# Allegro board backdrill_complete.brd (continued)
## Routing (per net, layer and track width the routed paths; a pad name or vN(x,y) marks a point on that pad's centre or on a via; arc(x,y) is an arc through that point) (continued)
P66_AD3: length 22.9
  TOP w0.127: 31.75,67.31 17.86,67.31 16.9,66.36 16.12,66.36 15.16,67.31 11.43,67.31 ; 53.15,32.58 U3D1.D2 53.31,32.44 52.73,33.02 53.02,32.72 53.15,32.59 53.15,32.58
P66_AD4: length 22.9
  TOP w0.127: 52.73,31.75 53.02,31.45 53.15,31.32 53.15,31.31 U3D1.E2 53.31,31.17 52.73,31.75
  LAYER_8 w0.127: 19.05,68.58 32.94,68.58 33.9,67.63 34.68,67.63 35.64,68.58 39.37,68.58
P66_AD5: length 22.9
  TOP w0.127: 13.97,68.58 17.7,68.58 18.66,67.63 19.44,67.63 20.4,68.58 34.29,68.58 ; 53.31,33.71 52.73,34.29 53.02,33.99 53.15,33.86 53.15,33.85 U3D1.C2 53.31,33.71
P66_AD6: length 22.9
  TOP w0.127: 16.51,69.85 30.4,69.85 31.36,68.9 32.14,68.9 33.1,69.85 36.83,69.85 ; U3D1.B2 53.31,34.98 52.73,35.56 53.02,35.26 53.15,35.13 53.15,35.12 U3D1.B2
P66_AD7: length 22.9
  TOP w0.127: 53.02,36.53 52.73,36.83 53.31,36.25 U3D1.A2 53.15,36.39 53.15,36.4 53.02,36.53
  BOTTOM w0.127: 13.97,71.12 17.7,71.12 18.66,70.17 19.44,70.17 20.4,71.12 34.29,71.12
P66_AD8: length 22.9
  TOP w0.127: 54,31.75 54.58,31.17 U3D1.E3 54.42,31.31 54.42,31.32 54.29,31.45 54,31.75
  LAYER_8 w0.127: 11.43,72.39 15.16,72.39 16.12,71.44 16.9,71.44 17.86,72.39 31.75,72.39
P66_AD9: length 22.9
  TOP w0.127: 54,35.56 54.58,34.98 U3D1.B3 54.42,35.12 54.42,35.13 54.29,35.26 54,35.56
  LAYER_8 w0.127: 39.37,76.2 35.64,76.2 34.68,75.25 33.9,75.25 32.94,76.2 19.05,76.2
P66_AD10: length 22.9
  TOP w0.127: 55.56,32.72 55.27,33.02 55.85,32.44 U3D1.D4 55.69,32.58 55.69,32.59 55.56,32.72
  BOTTOM w0.127: 31.75,77.47 19.74,77.47 19.71,77.44 17.83,77.44 16.9,76.52 16.12,76.52 15.16,77.47 11.43,77.47
P66_AD11: length 22.9
  TOP w0.127: 55.27,31.75 55.85,31.17 U3D1.E4 55.69,31.31 55.69,31.32 55.56,31.45 55.27,31.75
  LAYER_8 w0.127: 39.37,78.74 35.64,78.74 34.68,77.79 33.9,77.79 32.94,78.74 19.05,78.74
P66_AD12: length 22.9
  TOP w0.127: 55.27,34.29 55.85,33.71 U3D1.C4 55.69,33.85 55.69,33.86 55.56,33.99 55.27,34.29
  BOTTOM w0.127: 13.97,78.74 17.55,78.74 18.54,77.75 19.58,77.75 20.57,78.74 34.29,78.74
P66_AD13: length 22.9
  TOP w0.127: 55.69,35.12 55.69,35.13 55.56,35.26 55.27,35.56 55.85,34.98 U3D1.B4 55.69,35.12
  BOTTOM w0.127: 16.51,80.01 30.4,80.01 31.36,79.06 32.14,79.06 33.1,80.01 36.83,80.01
P66_AD14: length 22.9
  TOP w0.127: 55.85,36.25 55.27,36.83 55.56,36.53 55.69,36.4 55.69,36.39 U3D1.A4 55.85,36.25
  BOTTOM w0.127: 13.97,81.28 17.7,81.28 18.66,80.33 19.44,80.33 20.4,81.28 34.29,81.28
P66_AD15: length 22.9
  TOP w0.127: 56.96,35.13 56.83,35.26 56.54,35.56 57.12,34.98 U3D1.B5 56.96,35.12 56.96,35.13
  LAYER_8 w0.127: 16.51,82.55 30.4,82.55 31.36,81.6 32.14,81.6 33.1,82.55 36.83,82.55
P66_AD16: length 22.9
  TOP w0.127: U3D1.D9 62.2,32.44 61.62,33.02 61.91,32.72 62.04,32.59 62.04,32.58 U3D1.D9
  LAYER_8 w0.127: 36.83,97.79 33.1,97.79 32.14,96.84 31.36,96.84 30.4,97.79 16.51,97.79
P66_AD17: length 22.9
  TOP w0.127: U3D1.C9 62.2,33.71 61.62,34.29 61.91,33.99 62.04,33.86 62.04,33.85 U3D1.C9
  LAYER_5 w0.127: 31.75,97.79 17.86,97.79 16.9,96.84 16.12,96.84 15.16,97.79 11.43,97.79
P66_AD18: length 22.9
  TOP w0.127: 62.04,36.4 61.91,36.53 61.62,36.83 62.2,36.25 U3D1.A9 62.04,36.39 62.04,36.4
  LAYER_5 w0.127: 19.05,99.06 32.94,99.06 33.9,98.11 34.68,98.11 35.64,99.06 39.37,99.06
P66_AD19: length 22.9
  TOP w0.127: 63.69,32.58 63.69,32.59 63.82,32.72 64.11,33.02 63.53,32.44 U3D1.D10 63.69,32.58
  LAYER_5 w0.127: 31.75,100.33 17.86,100.33 16.9,99.38 16.12,99.38 15.16,100.33 11.43,100.33
P66_AD20: length 22.9
  TOP w0.127: 64.11,34.29 63.82,33.99 63.69,33.86 63.69,33.85 U3D1.C10 63.53,33.71 64.11,34.29
  LAYER_8 w0.127: 19.05,101.6 32.94,101.6 33.9,100.65 34.68,100.65 35.64,101.6 39.37,101.6
P66_AD21: length 22.9
  TOP w0.127: 64.11,35.56 63.53,34.98 U3D1.B10 63.69,35.12 63.69,35.13 63.82,35.26 64.11,35.56
  LAYER_5 w0.127: 13.97,101.6 17.7,101.6 18.66,100.65 19.44,100.65 20.4,101.6 34.29,101.6
P66_AD22: length 22.9
  TOP w0.127: 64.11,36.83 63.82,36.53 63.69,36.4 63.69,36.39 U3D1.A10 63.53,36.25 64.11,36.83
  LAYER_3 w0.127: 36.83,102.87 33.1,102.87 32.14,101.92 31.36,101.92 30.4,102.87 16.51,102.87
P66_AD23: length 22.9
  TOP w0.127: U3D1.D11 64.96,32.58 64.96,32.59 65.09,32.72 65.38,33.02 64.8,32.44 U3D1.D11
  LAYER_3 w0.127: 34.29,104.14 20.4,104.14 19.44,103.19 18.66,103.19 17.7,104.14 13.97,104.14
P66_AD24: length 22.9
  TOP w0.127: 64.96,35.12 64.96,35.13 65.09,35.26 65.38,35.56 64.8,34.98 U3D1.B11 64.96,35.12
  LAYER_8 w0.127: 19.05,106.68 32.94,106.68 33.9,105.73 34.68,105.73 35.64,106.68 39.37,106.68
P66_AD25: length 22.9
  TOP w0.127: 65.38,36.83 65.09,36.53 64.96,36.4 64.96,36.39 U3D1.A11 64.8,36.25 65.38,36.83
  LAYER_3 w0.127: 31.75,107.95 17.86,107.95 16.9,107 16.12,107 15.16,107.95 11.43,107.95
P66_AD26: length 124.8
  TOP w0.127: 66.36,32.72 66.65,33.02 66.07,32.44 U3D1.D12 66.23,32.58 66.23,32.59 66.36,32.72
  LAYER_6 w0.127: 66.65,33.02 66.83,33.2 66.83,33.75 67.16,34.08 67.16,37.04 66.83,37.37 66.83,38.51 66.7,38.63 42.9,38.63 40.61,40.92 40.61,108.03 39.42,109.22 39.37,109.22
  LAYER_8 w0.127: 39.37,109.22 35.64,109.22 34.68,108.27 33.9,108.27 32.94,109.22 19.05,109.22
P66_AD27: length 22.9
  TOP w0.127: 34.29,109.22 20.4,109.22 19.44,108.27 18.66,108.27 17.7,109.22 13.97,109.22 ; U3D1.C12 66.23,33.85 66.23,33.86 66.36,33.99 66.65,34.29 66.07,33.71 U3D1.C12
P66_AD28: length 22.9
  TOP w0.127: 36.83,110.49 33.1,110.49 32.14,109.54 31.36,109.54 30.4,110.49 16.51,110.49 ; U3D1.A12 66.07,36.25 66.65,36.83 66.36,36.53 66.23,36.4 66.23,36.39 U3D1.A12
P66_AD29: length 22.9
  TOP w0.127: 34.29,111.76 20.4,111.76 19.44,110.81 18.66,110.81 17.7,111.76 13.97,111.76 ; 67.34,33.71 U3D1.C13 67.5,33.85 67.5,33.86 67.63,33.99 67.92,34.29 67.34,33.71
P66_AD30: length 22.8
  TOP w0.127: 67.34,34.98 U3D1.B13 67.5,35.12 67.5,35.13 67.63,35.26 67.92,35.56 67.34,34.98
  LAYER_8 w0.127: 16.51,113.03 30.45,113.03 31.37,112.12 32.11,112.12 33.02,113.03 36.83,113.03
P66_AD31: length 22.9
  TOP w0.127: 31.75,113.03 17.86,113.03 16.9,112.08 16.12,112.08 15.16,113.03 11.43,113.03 ; 67.5,36.39 U3D1.A13 67.34,36.25 67.92,36.83 67.63,36.53 67.5,36.4 67.5,36.39
P66_AD32: length 37.5
  TOP w0.127: 19.05,20.32 32.94,20.32 33.9,19.37 34.68,19.37 35.64,20.32 47.12,20.32 50.8,16.64 52.19,16.64 52.51,16.96 52.51,17.34 52.83,17.65 U3D1.T2
P66_AD33: length 44.1
  TOP w0.127: 51.46,17.73 52.04,17.14 U3D1.T1
  LAYER_5 w0.127: 31.75,21.59 17.86,21.59 16.9,20.64 16.12,20.64 15.16,21.59 11.43,21.59
  LAYER_8 w0.127: 31.75,21.59 35.48,21.59 36.44,20.64 37.22,20.64 38.18,21.59 47.6,21.59 51.46,17.73
P66_AD34: length 22
  TOP w0.127: 55.88,18.41 55.8,18.41 55.25,18.97 55.3,19.02
  LAYER_3 w0.127: 39.37,22.86 35.64,22.86 34.68,21.91 33.9,21.91 32.94,22.86 19.05,22.86
P66_AD35: length 44.2
  TOP w0.127: 54.05,19 54.64,18.41 54.61,18.41
  LAYER_5 w0.127: 13.97,22.86 17.7,22.86 18.66,21.91 19.44,21.91 20.4,22.86 34.29,22.86
  LAYER_8 w0.127: 54.05,19 53.92,18.87 53.17,18.87 52.84,18.54 51.08,18.54 47.07,22.56 40.41,22.56 39.76,21.91 38.98,21.91 38.02,22.86 34.29,22.86
P66_AD36: length 22.1
  TOP w0.127: 53.26,18.52 53.24,18.52 ; 53.26,18.52 53.34,18.41 ; 53.26,18.52 52.68,19.1
  LAYER_5 w0.127: 36.83,24.13 33.1,24.13 32.14,23.18 31.36,23.18 30.4,24.13 16.51,24.13
P66_AD37: length 44.3
  TOP w0.127: 52.07,18.41 52.04,18.47 51.46,19.05 51.75,18.75 51.88,18.62 51.88,18.61 52.07,18.41
  LAYER_5 w0.127: 34.29,25.4 20.4,25.4 19.44,24.45 18.66,24.45 17.7,25.4 13.97,25.4
  LAYER_8 w0.127: 51.46,19.05 46.37,24.14 38.19,24.14 37.22,23.18 36.44,23.18 35.88,23.74 35.88,25.22 35.7,25.4 34.29,25.4
P66_AD38: length 22.9
  TOP w0.127: 55.69,19.89 55.69,19.88 U3D1.P4 55.85,19.74 55.27,20.32 55.56,20.02 55.69,19.89
  LAYER_3 w0.127: 16.51,26.67 30.4,26.67 31.36,25.72 32.14,25.72 33.1,26.67 36.83,26.67
P66_AD39: length 48.5
  TOP w0.127: 54.58,19.74 54,20.32 54.29,20.02 54.42,19.89 54.42,19.88 U3D1.P3 54.58,19.74
  LAYER_5 w0.127: 31.75,26.67 17.86,26.67 16.9,25.72 16.12,25.72 15.16,26.67 11.43,26.67
  LAYER_8 w0.127: 54,20.32 53.47,20.85 53.39,20.85 53.16,21.08 52.52,21.08 52.22,21.38 52.22,21.8 51.67,22.35 51.25,22.35 50.95,22.65 49.51,22.65 47.07,25.1 40.41,25.1 39.76,24.45 38.98,24.45 38.33,25.1 37.22,25.1 36.6,25.72 36.44,25.72 35.48,26.67 31.75,26.67
P66_AD40: length 38.1
  TOP w0.127: 52.04,19.74 U3D1.P1 51.88,19.88 51.88,19.89 51.75,20.02 51.46,20.32 52.04,19.74
  LAYER_5 w0.127: 19.05,27.94 32.94,27.94 33.9,26.99 34.68,26.99 35.64,27.94 41.45,27.94 48.41,20.98 50.8,20.98 51.46,20.32
P66_AD41: length 50
  TOP w0.127: 55.56,21.29 55.27,21.59 55.85,21.01 U3D1.N4 55.69,21.15 55.69,21.16 55.56,21.29
  LAYER_5 w0.127: 31.75,29.21 17.86,29.21 16.9,28.26 16.12,28.26 15.16,29.21 11.43,29.21
  LAYER_8 w0.127: 55.27,21.59 54.51,22.35 53.79,22.35 53.49,22.65 53.49,23.07 52.94,23.62 52.52,23.62 52.22,23.92 52.22,24.34 51.67,24.89 48.58,24.89 46.53,26.95 37.9,26.95 37.22,27.62 37.07,27.62 35.48,29.21 31.75,29.21
P66_AD42: length 22.9
  TOP w0.127: 54,21.59 54.29,21.29 54.42,21.16 54.42,21.15 U3D1.N3 54.58,21.01 54,21.59
  LAYER_3 w0.127: 39.37,30.48 35.64,30.48 34.68,29.53 33.9,29.53 32.94,30.48 19.05,30.48
P66_AD43: length 45.4
  TOP w0.127: 53.31,21.01 52.73,21.59 53.02,21.29 53.15,21.16 53.15,21.15 U3D1.N2 53.31,21.01
  LAYER_5 w0.127: 13.97,30.48 17.7,30.48 18.66,29.53 19.44,29.53 20.4,30.48 38.02,30.48 38.98,29.53 40.78,29.53 49.02,21.29 51.05,21.29 51.25,21.08 51.67,21.08 52,21.41 52.55,21.41 52.73,21.59
P66_AD44: length 41.7
  TOP w0.127: 51.88,21.16 51.75,21.29 51.46,21.59 52.04,21.01 U3D1.N1 51.88,21.15 51.88,21.16
  LAYER_5 w0.127: 51.46,21.59 50.62,21.59 40.46,31.75 33.1,31.75 32.14,30.8 31.36,30.8 30.4,31.75 16.51,31.75
P66_AD45: length 48.7
  TOP w0.127: 55.69,22.43 55.56,22.56 55.27,22.86 55.85,22.28 U3D1.M4 55.69,22.42 55.69,22.43
  LAYER_5 w0.127: 55.27,22.86 54.51,22.1 53.16,22.1 52.91,22.35 51.11,22.35 50.86,22.61 50.86,22.65 46.56,26.95 46.53,26.95 41.41,32.07 38.98,32.07 38.02,33.02 20.4,33.02 19.44,32.07 18.66,32.07 17.7,33.02 13.97,33.02
P66_AD46: length 22.9
  TOP w0.127: U3D1.M3 54.58,22.28 54,22.86 54.29,22.56 54.42,22.43 54.42,22.42 U3D1.M3
  LAYER_3 w0.127: 16.51,34.29 30.4,34.29 31.36,33.34 32.14,33.34 33.1,34.29 36.83,34.29
P66_AD47: length 49.9
  TOP w0.127: 53.15,22.43 53.15,22.42 U3D1.M2 53.31,22.28 52.73,22.86 53.02,22.56 53.15,22.43
  LAYER_5 w0.127: 52.73,22.86 52.53,23.06 52.53,23.16 52.07,23.62 51.25,23.62 51.15,23.72 51.13,23.72 50.88,23.98 50.88,24.64 48.34,27.18 48.34,27.25 41.3,34.29 38.18,34.29 37.22,33.34 36.44,33.34 35.48,34.29 17.86,34.29 16.9,33.34 16.12,33.34 15.16,34.29 11.43,34.29
P66_AD48: length 22.9
  TOP w0.127: 51.46,22.86 52.04,22.28 U3D1.M1 51.88,22.42 51.88,22.43 51.75,22.56 51.46,22.86
  LAYER_5 w0.127: 19.05,35.56 32.94,35.56 33.9,34.61 34.68,34.61 35.64,35.56 39.37,35.56
P66_AD49: length 22.9
  TOP w0.127: U3D1.L4 55.69,23.69 55.69,23.7 55.56,23.83 55.27,24.13 55.85,23.55 U3D1.L4
  LAYER_5 w0.127: 31.75,36.83 17.86,36.83 16.9,35.88 16.12,35.88 15.16,36.83 11.43,36.83
P66_AD50: length 22.9
  TOP w0.127: 54.29,23.83 54,24.13 54.58,23.55 U3D1.L3 54.42,23.69 54.42,23.7 54.29,23.83
  LAYER_8 w0.127: 39.37,38.1 35.64,38.1 34.68,37.15 33.9,37.15 32.94,38.1 19.05,38.1
P66_AD51: length 22.9
  TOP w0.127: 53.15,23.7 53.15,23.69 U3D1.L2 53.31,23.55 52.73,24.13 53.02,23.83 53.15,23.7
  LAYER_5 w0.127: 13.97,38.1 17.7,38.1 18.66,37.15 19.44,37.15 20.4,38.1 34.29,38.1
P66_AD52: length 22.9
  TOP w0.127: U3D1.L1 52.04,23.55 51.46,24.13 51.75,23.83 51.88,23.7 51.88,23.69 U3D1.L1
  LAYER_5 w0.127: 16.51,39.37 30.4,39.37 31.36,38.42 32.14,38.42 33.1,39.37 36.83,39.37
P66_AD53: length 22.9
  TOP w0.127: 55.69,24.97 55.56,25.1 55.27,25.4 55.85,24.82 U3D1.K4 55.69,24.96 55.69,24.97
  LAYER_5 w0.127: 13.97,40.64 17.7,40.64 18.66,39.69 19.44,39.69 20.4,40.64 34.29,40.64
P66_AD54: length 22.9
  TOP w0.127: 54.42,24.96 54.42,24.97 54.29,25.1 54,25.4 54.58,24.82 U3D1.K3 54.42,24.96
  LAYER_3 w0.127: 16.51,41.91 30.4,41.91 31.36,40.96 32.14,40.96 33.1,41.91 36.83,41.91
P66_AD55: length 22.9
  TOP w0.127: U3D1.K1 52.04,24.82 51.46,25.4 51.75,25.1 51.88,24.97 51.88,24.96 U3D1.K1
  LAYER_5 w0.127: 31.75,41.91 17.86,41.91 16.9,40.96 16.12,40.96 15.16,41.91 11.43,41.91
P66_AD56: length 22.9
  TOP w0.127: 55.85,26.09 U3D1.J4 55.69,26.23 55.69,26.24 55.56,26.37 55.27,26.67 55.85,26.09
  LAYER_5 w0.127: 39.37,43.18 35.64,43.18 34.68,42.23 33.9,42.23 32.94,43.18 19.05,43.18
P66_AD57: length 22.9
  TOP w0.127: 54,26.67 54.58,26.09 U3D1.J3 54.42,26.23 54.42,26.24 54.29,26.37 54,26.67
  LAYER_5 w0.127: 11.43,44.45 15.16,44.45 16.12,43.5 16.9,43.5 17.86,44.45 31.75,44.45
P66_AD58: length 22.9
  TOP w0.127: 53.02,26.37 53.15,26.24 53.15,26.23 U3D1.J2 53.31,26.09 52.73,26.67 53.02,26.37
  LAYER_3 w0.127: 39.37,45.72 35.64,45.72 34.68,44.77 33.9,44.77 32.94,45.72 19.05,45.72
P66_AD59: length 22.9
  TOP w0.127: 51.46,26.67 51.75,26.37 51.88,26.24 51.88,26.23 U3D1.J1 52.04,26.09 51.46,26.67
  LAYER_5 w0.127: 34.29,45.72 20.4,45.72 19.44,44.77 18.66,44.77 17.7,45.72 13.97,45.72
P66_AD60: length 22.9
  TOP w0.127: 55.85,27.36 U3D1.H4 55.69,27.5 55.69,27.51 55.56,27.64 55.27,27.94 55.85,27.36
  LAYER_5 w0.127: 16.51,46.99 30.4,46.99 31.36,46.04 32.14,46.04 33.1,46.99 36.83,46.99
P66_AD61: length 22.9
  TOP w0.127: 54.29,27.64 54,27.94 54.58,27.36 U3D1.H3 54.42,27.5 54.42,27.51 54.29,27.64
  LAYER_5 w0.127: 13.97,48.26 17.7,48.26 18.66,47.31 19.44,47.31 20.4,48.26 34.29,48.26
P66_AD62: length 22.9
  TOP w0.127: 52.73,27.94 53.02,27.64 53.15,27.51 53.15,27.5 U3D1.H2 53.31,27.36 52.73,27.94
  LAYER_3 w0.127: 16.51,49.53 30.4,49.53 31.36,48.58 32.14,48.58 33.1,49.53 36.83,49.53
P66_AD63: length 22.9
  TOP w0.127: 52.04,27.36 51.46,27.94 51.75,27.64 51.88,27.51 51.88,27.5 U3D1.H1 52.04,27.36
  LAYER_5 w0.127: 11.43,49.53 15.16,49.53 16.12,48.58 16.9,48.58 17.86,49.53 31.75,49.53
P66_C_BE_L0: length 1.8
  TOP w0.127: U3D1.D3 54.42,32.58 54.42,32.59 54.29,32.72 54,33.02 54.58,32.44 U3D1.D3
P66_C_BE_L1: length 22.9
  TOP w0.127: U3D1.A5 57.12,36.25 56.54,36.83 56.83,36.53 56.96,36.4 56.96,36.39 U3D1.A5
  BOTTOM w0.127: 31.75,82.55 17.86,82.55 16.9,81.6 16.12,81.6 15.16,82.55 11.43,82.55
P66_C_BE_L2: length 22.9
  TOP w0.127: 60.93,36.25 U3D1.A8 60.77,36.39 60.77,36.4 60.64,36.53 60.35,36.83 60.93,36.25
  LAYER_6 w0.127: 34.29,96.52 20.4,96.52 19.44,95.57 18.66,95.57 17.7,96.52 13.97,96.52
P66_C_BE_L3: length 22.9
  TOP w0.127: 65.38,34.29 65.09,33.99 64.96,33.86 64.96,33.85 U3D1.C11 64.8,33.71 65.38,34.29
  LAYER_3 w0.127: 11.43,105.41 15.16,105.41 16.12,104.46 16.9,104.46 17.86,105.41 31.75,105.41
P66_C_BE_L4: length 22.9
  TOP w0.127: 56.83,28.91 56.54,29.21 57.12,28.63 U3D1.G5 56.96,28.77 56.96,28.78 56.83,28.91
  LAYER_5 w0.127: 11.43,52.07 15.16,52.07 16.12,51.12 16.9,51.12 17.86,52.07 31.75,52.07
P66_C_BE_L5: length 22.9
  TOP w0.127: 54.58,28.63 U3D1.G3 54.42,28.77 54.42,28.78 54.29,28.91 54,29.21 54.58,28.63
  LAYER_3 w0.127: 19.05,53.34 32.94,53.34 33.9,52.39 34.68,52.39 35.64,53.34 39.37,53.34
P66_C_BE_L6: length 22.9
  TOP w0.127: 53.15,28.77 U3D1.G2 53.31,28.63 52.73,29.21 53.02,28.91 53.15,28.78 53.15,28.77
  LAYER_5 w0.127: 34.29,53.34 20.4,53.34 19.44,52.39 18.66,52.39 17.7,53.34 13.97,53.34
P66_C_BE_L7: length 22.9
  TOP w0.127: 51.88,28.78 51.88,28.77 U3D1.G1 52.04,28.63 51.46,29.21 51.75,28.91 51.88,28.78
  LAYER_5 w0.127: 16.51,54.61 30.4,54.61 31.36,53.66 32.14,53.66 33.1,54.61 36.83,54.61
P66_DEVSEL_L: length 22.9
  TOP w0.127: 59.5,36.39 59.5,36.4 59.37,36.53 59.08,36.83 59.66,36.25 U3D1.A7 59.5,36.39
  LAYER_6 w0.127: 13.97,91.44 17.7,91.44 18.66,90.49 19.44,90.49 20.4,91.44 34.29,91.44
P66_FRAME_L: length 22.9
  TOP w0.127: 60.77,35.12 U3D1.B8 60.93,34.98 60.35,35.56 60.64,35.26 60.77,35.13 60.77,35.12
  LAYER_6 w0.127: 36.83,95.25 33.1,95.25 32.14,94.3 31.36,94.3 30.4,95.25 16.51,95.25
P66_GNT_L0: length 136.5
  TOP w0.127: 72.58,35.13 72.71,35.26 73,35.56 72.42,34.98 U3D1.B17 72.58,35.12 72.58,35.13
  LAYER_5 w0.127: 19.05,116.84 32.94,116.84 33.9,115.89 34.68,115.89 35.64,116.84 38.02,116.84 38.98,115.89 39.76,115.89 40.72,116.84 43.28,116.84 43.84,116.28 43.84,41.58 44.93,40.49 70.46,40.49 71.22,39.73 71.22,36.62 71.52,36.32 72.24,36.32 73,35.56
P66_GNT_L1: length 116
  TOP w0.127: 71.31,33.86 71.44,33.99 71.73,34.29 71.15,33.71 U3D1.C16 71.31,33.85 71.31,33.86
  LAYER_6 w0.127: 71.73,34.29 72.01,34.57 72.01,35.12 72.24,35.35 72.24,35.77 72.01,36 72.01,36.39 72.24,36.62 72.24,37.04 72.01,37.27 72.01,38.96 71.42,39.55 43,39.55 41.3,41.25 41.3,116.71 41.17,116.84 39.37,116.84
P66_IRDY_L: length 22.9
  TOP w0.127: 60.35,34.29 60.64,33.99 60.77,33.86 60.77,33.85 U3D1.C8 60.93,33.71 60.35,34.29
  LAYER_6 w0.127: 13.97,93.98 17.7,93.98 18.66,93.03 19.44,93.03 20.4,93.98 34.29,93.98
P66_IRQ_L0: length 1.8
  TOP w0.127: 72.71,20.02 72.58,19.89 72.58,19.88 U3D1.P17 72.42,19.74 73,20.32 72.71,20.02
P66_IRQ_L1: length 1.8
  TOP w0.127: 71.31,19.88 U3D1.P16 71.15,19.74 71.73,20.32 71.44,20.02 71.31,19.89 71.31,19.88
P66_IRQ_L2: length 1.8
  TOP w0.127: U3D1.P15 69.88,19.74 70.46,20.32 70.17,20.02 70.04,19.89 70.04,19.88 U3D1.P15
P66_IRQ_L3: length 1.8
  TOP w0.127: 72.42,21.01 73,21.59 72.71,21.29 72.58,21.16 72.58,21.15 U3D1.N17 72.42,21.01
P66_IRQ_L4: length 179.1
  TOP w0.127: 71.31,21.15 71.31,21.16 71.44,21.29 71.73,21.59 71.15,21.01 U3D1.N16 71.31,21.15
  LAYER_3 w0.127: 71.73,21.59 72.31,21.01 76.84,21.01 77.34,20.5 77.34,20.22
  LAYER_5 w0.127: 16.51,130.81 30.4,130.81 31.36,129.86 32.14,129.86 33.1,130.81 35.48,130.81 36.44,129.86 37.22,129.86 37.82,130.45 38.94,130.45 38.98,130.49 39.76,130.49 39.8,130.45 46.71,130.45 47.78,129.39 47.78,43.84 48.08,43.54 75.9,43.54 77.5,41.94 77.5,24.54 77.34,24.39 77.34,20.22
P66_IRQ_L5: length 179.6
  TOP w0.127: 70.04,21.16 70.04,21.15 U3D1.N15 69.88,21.01 70.46,21.59 70.17,21.29 70.04,21.16
  LAYER_3 w0.127: 70.46,21.59 71.22,20.83 71.94,20.83 72.24,20.53 72.24,20.36 72.79,19.81 73.21,19.81 73.69,20.29 76.05,20.29
  LAYER_5 w0.127: 13.97,129.54 17.7,129.54 18.66,128.59 19.44,128.59 20.4,129.54 32.94,129.54 33.9,128.59 34.68,128.59 35.64,129.54 38.02,129.54 38.98,128.59 39.76,128.59 40.13,128.96 45.52,128.96 46.66,127.81 46.66,42.95 47.09,42.52 74.8,42.52 76.05,41.27 76.05,20.29
P66_IRQ_L6: length 183
  TOP w0.127: 68.77,21.15 68.77,21.16 68.9,21.29 69.19,21.59 68.61,21.01 U3D1.N14 68.77,21.15
  LAYER_3 w0.127: 79.76,20.29 77.98,22.07 73.24,22.07 73.21,22.1 69.7,22.1 69.19,21.59
  LAYER_6 w0.127: 69.95,22.35 69.19,21.59 ; 19.05,129.54 32.94,129.54 33.9,130.49 34.46,130.49 36.09,132.13 37.08,132.13 38.07,131.14 38.96,131.14 38.98,131.13 46.98,131.13 48.18,129.92 48.18,45.26 49.2,44.25 74.47,44.25 78.18,40.54 78.18,21.89 79.76,20.32 79.76,20.29
P66_IRQ_L7: length 170.3
  TOP w0.127: 72.42,22.28 73,22.86 72.71,22.56 72.58,22.43 72.58,22.42 U3D1.M17 72.42,22.28
  LAYER_5 w0.127: 73,22.86 74.17,24.03 74.17,40.06 72.62,41.61 46.13,41.61 45.14,42.6 45.14,127.05 44.87,127.32 40.4,127.32 39.76,127.95 38.98,127.95 38.34,127.32 36.44,127.32 35.48,128.27 33.1,128.27 32.14,127.32 31.36,127.32 30.4,128.27 17.86,128.27 16.9,127.32 16.12,127.32 15.16,128.27 11.43,128.27
P66_IRQ_L8: length 152
  TOP w0.127: 70.17,22.56 70.04,22.43 70.04,22.42 U3D1.M15 69.88,22.28 70.46,22.86 70.17,22.56
  LAYER_6 w0.127: 36.83,130.81 36.83,130.2 38.61,128.42 45.39,128.42 46.02,127.79 46.02,42.77 46.66,42.14 74.5,42.14 76.79,39.85 76.79,27.46 77.44,26.8 77.44,26.13 75.95,24.64 72.79,24.64 72.24,24.09 72.24,23.92 71.69,23.37 71.52,23.37 71.33,23.18 70.78,23.18 70.46,22.86
P66_IRQ_L9: length 155.1
  TOP w0.127: 68.77,22.43 68.9,22.56 69.19,22.86 68.61,22.28 U3D1.M14 68.77,22.42 68.77,22.43
  LAYER_6 w0.127: 34.29,129.54 34.29,128.7 35.67,127.32 37.4,127.32 38.38,126.34 38.68,126.34 38.98,126.05 39.76,126.05 40.06,126.34 43.71,126.34 44.35,125.7 44.35,41.58 44.98,40.94 74.73,40.94 76.05,39.62 76.05,27.35 76.42,26.97 76.84,26.97 77.14,26.68 77.14,26.26 76.84,25.96 76.42,25.96 76.37,25.91 72.79,25.91 72.49,25.61 72.49,24.77 72.36,24.64 70.25,24.64 69.95,24.34 69.95,23.62 69.19,22.86
P66_IRQ_L10: length 154.9
  TOP w0.127: 78.51,20.29 78.51,21.54 75.97,24.08 73.05,24.08 73,24.13 ; 73,24.13 72.71,23.83 72.58,23.7 72.58,23.69 U3D1.L17 72.42,23.55 73,24.13
  LAYER_6 w0.127: 39.37,129.54 46.61,129.54 47.24,128.91 47.24,43.71 47.88,43.08 74.57,43.08 77.52,40.13 77.52,27.16 77.75,26.93 77.75,21.06 78.51,20.29
P66_IRQ_L11: length 151.8
  TOP w0.127: 71.44,23.83 71.73,24.13 71.15,23.55 U3D1.L16 71.31,23.69 71.31,23.7 71.44,23.83
  LAYER_3 w0.127: 76.63,26.47 76.63,24.79 75.97,24.13 73.72,24.13 73.21,23.62 72.79,23.62 72.28,24.13 71.73,24.13
  LAYER_6 w0.127: 31.75,128.27 32.74,128.27 33.34,127.67 33.34,126.61 33.9,126.05 34.96,126.05 37.52,123.49 42.24,123.49 42.88,122.86 42.88,41.38 44.12,40.13 74.57,40.13 75.36,39.34 75.36,26.8 75.69,26.47 76.63,26.47
P66_IRQ_L12: length 1.8
  TOP w0.127: 70.04,23.7 70.17,23.83 70.46,24.13 69.88,23.55 U3D1.L15 70.04,23.69 70.04,23.7
P66_IRQ_L13: length 1.8
  TOP w0.127: 68.77,23.69 68.77,23.7 68.9,23.83 69.19,24.13 68.61,23.55 U3D1.L14 68.77,23.69
P66_IRQ_L14: length 1.8
  TOP w0.127: U3D1.K16 71.31,24.96 71.31,24.97 71.44,25.1 71.73,25.4 71.15,24.82 U3D1.K16
P66_IRQ_L15: length 1.8
  TOP w0.127: 69.88,24.82 U3D1.K15 70.04,24.96 70.04,24.97 70.17,25.1 70.46,25.4 69.88,24.82
P66_IRQ_L16: length 1.8
  TOP w0.127: 69.19,25.4 68.61,24.82 U3D1.K14 68.77,24.96 68.77,24.97 68.9,25.1 69.19,25.4
P66_IRQ_L17: length 1.8
  TOP w0.127: 72.58,26.24 72.71,26.37 73,26.67 72.42,26.09 U3D1.J17 72.58,26.23 72.58,26.24
P66_IRQ_L18: length 1.8
  TOP w0.127: 70.46,26.67 69.88,26.09 U3D1.J15 70.04,26.23 70.04,26.24 70.17,26.37 70.46,26.67
P66_IRQ_L19: length 1.8
  TOP w0.127: 68.77,26.23 68.77,26.24 68.9,26.37 69.19,26.67 68.61,26.09 U3D1.J14 68.77,26.23
P66_IRQ_L20: length 1.8
  TOP w0.127: 71.44,27.64 71.73,27.94 71.15,27.36 U3D1.H16 71.31,27.5 71.31,27.51 71.44,27.64
P66_IRQ_L21: length 1.8
  TOP w0.127: 70.17,27.64 70.46,27.94 69.88,27.36 U3D1.H15 70.04,27.5 70.04,27.51 70.17,27.64
P66_IRQ_L22: length 1.8
  TOP w0.127: 68.61,27.36 U3D1.H14 68.77,27.5 68.77,27.51 68.9,27.64 69.19,27.94 68.61,27.36
P66_IRQ_L23: length 1.8
  TOP w0.127: U3D1.G17 72.58,28.77 72.58,28.78 72.71,28.91 73,29.21 72.42,28.63 U3D1.G17
P66_LOCK_L: length 22.9
  TOP w0.127: 59.66,33.71 59.08,34.29 59.37,33.99 59.5,33.86 59.5,33.85 U3D1.C7 59.66,33.71
  LAYER_8 w0.127: 13.97,88.9 17.7,88.9 18.66,87.95 19.44,87.95 20.4,88.9 34.29,88.9
P66_M66EN: length 22.9
  TOP w0.127: 54.42,36.39 U3D1.A3 54.58,36.25 54,36.83 54.29,36.53 54.42,36.4 54.42,36.39
  BOTTOM w0.127: 34.29,76.2 20.4,76.2 19.44,75.25 18.66,75.25 17.7,76.2 13.97,76.2
P66_PAR: length 22.9
  TOP w0.127: 58.23,32.59 58.1,32.72 57.81,33.02 58.39,32.44 U3D1.D6 58.23,32.58 58.23,32.59
  LAYER_8 w0.127: 39.37,83.82 35.64,83.82 34.68,82.87 33.9,82.87 32.94,83.82 19.05,83.82
P66_PAR64: length 22.9
  TOP w0.127: 55.27,29.21 55.85,28.63 U3D1.G4 55.69,28.77 55.69,28.78 55.56,28.91 55.27,29.21
  LAYER_5 w0.127: 39.37,50.8 35.64,50.8 34.68,49.85 33.9,49.85 32.94,50.8 19.05,50.8
P66_PCIRST_L: length 21.1
  LAYER_3 w0.127: 19.05,119.38 32.94,119.38 33.9,118.43 34.68,118.43 35.64,119.38 39.37,119.38
P66_PERR_L: length 22.9
  TOP w0.127: 59.66,32.44 59.08,33.02 59.37,32.72 59.5,32.59 59.5,32.58 U3D1.D7 59.66,32.44
  LAYER_8 w0.127: 31.75,87.63 17.86,87.63 16.9,86.68 16.12,86.68 15.16,87.63 11.43,87.63
P66_REQ64_L: length 22.9
  TOP w0.127: 54.42,30.05 54.29,30.18 54,30.48 54.58,29.9 U3D1.F3 54.42,30.04 54.42,30.05
  LAYER_8 w0.127: 16.51,62.23 30.4,62.23 31.36,61.28 32.14,61.28 33.1,62.23 36.83,62.23
P66_REQ_L0: length 139.4
  TOP w0.127: 70.04,36.39 U3D1.A15 69.88,36.25 70.46,36.83 70.17,36.53 70.04,36.4 70.04,36.39
  LAYER_3 w0.127: 11.43,115.57 12,115 13.33,115 13.58,115.25 15.05,115.25 15.68,114.62 17.79,114.62 18.87,115.7 21.18,115.7 22.12,116.64 32.79,116.64 34.14,115.29 35.1,115.29 35.78,114.62 37.3,114.62 37.93,115.25 41.21,115.25 41.53,114.93 42.29,114.93
  LAYER_5 w0.127: 70.46,36.83 70.23,37.06 70.23,37.97 68.35,39.85 43.81,39.85 42.29,41.38 42.29,114.93
P66_REQ_L1: length 1.8
  TOP w0.127: 68.9,32.72 69.19,33.02 68.61,32.44 U3D1.D14 68.77,32.58 68.77,32.59 68.9,32.72
P66_REQ_L2: length 1.8
  TOP w0.127: 69.19,34.29 68.61,33.71 U3D1.C14 68.77,33.85 68.77,33.86 68.9,33.99 69.19,34.29
P66_REQ_L3: length 1.8
  TOP w0.127: U3D1.B14 68.77,35.12 68.77,35.13 68.9,35.26 69.19,35.56 68.61,34.98 U3D1.B14
P66_REQ_L4: length 1.8
  TOP w0.127: 68.61,36.25 69.19,36.83 68.9,36.53 68.77,36.4 68.77,36.39 U3D1.A14 68.61,36.25
P66_REQ_L5: length 1.8
  TOP w0.127: 67.5,32.58 67.5,32.59 67.63,32.72 67.92,33.02 67.34,32.44 U3D1.D13 67.5,32.58
P66_SERR_L: length 22.9
  TOP w0.127: U3D1.C6 58.23,33.85 58.23,33.86 58.1,33.99 57.81,34.29 58.39,33.71 U3D1.C6
  LAYER_8 w0.127: 31.75,85.09 17.86,85.09 16.9,84.14 16.12,84.14 15.16,85.09 11.43,85.09
P66_STOP_L: length 22.9
  TOP w0.127: 59.08,35.56 59.37,35.26 59.5,35.13 59.5,35.12 U3D1.B7 59.66,34.98 59.08,35.56
  LAYER_8 w0.127: 16.51,90.17 30.4,90.17 31.36,89.22 32.14,89.22 33.1,90.17 36.83,90.17
P66_TCK: length 21.1
  LAYER_3 w0.127: 31.75,135.89 17.86,135.89 16.9,134.94 16.12,134.94 15.16,135.89 11.43,135.89
P66_TDI: length 21.1
  LAYER_3 w0.127: 16.51,133.35 30.4,133.35 31.36,132.4 32.14,132.4 33.1,133.35 36.83,133.35
P66_TMS: length 21.1
  TOP w0.127: 19.05,134.62 32.94,134.62 33.9,133.67 34.68,133.67 35.64,134.62 39.37,134.62
P66_TRDY_L: length 22.9
  TOP w0.127: 60.77,32.58 U3D1.D8 60.93,32.44 60.35,33.02 60.64,32.72 60.77,32.59 60.77,32.58
  LAYER_6 w0.127: 36.83,92.71 33.1,92.71 32.14,91.76 31.36,91.76 30.4,92.71 16.51,92.71
P66_TRST_L: length 21.1
  LAYER_3 w0.127: 39.37,137.16 36.06,137.16 35.12,136.22 33.46,136.22 32.52,137.16 19.05,137.16
P_PME_L: length 75.9
  LAYER_3 w0.127: 92.71,114.3 78.75,114.3 77.84,113.4 77.1,113.4 76.19,114.3 55.89,114.3 54.98,113.4 54.24,113.4 53.33,114.3 35.64,114.3 34.68,113.35 33.9,113.35 32.94,114.3 19.05,114.3
PAR_L: length 33.8
  LAYER_8 w0.127: 59.69,83.82 76.19,83.82 77.1,82.92 77.84,82.92 78.75,83.82 92.71,83.82
PCI6_66MHZ_CLK: length 1.8
  TOP w0.127: 51.46,31.75 51.75,31.45 51.88,31.32 51.88,31.31 U3D1.E1 52.04,31.17 51.46,31.75
PCIRST_L: length 33.8
  LAYER_6 w0.127: 59.69,119.38 76.19,119.38 77.1,118.48 77.84,118.48 78.75,119.38 92.71,119.38
PERR_L: length 50.5
  TOP w0.127: 100.33,87.63 96.53,87.63 95.62,86.73 94.88,86.73 93.97,87.63 76.21,87.63 75.3,86.73 74.56,86.73 73.65,87.63 58.43,87.63 57.52,86.73 56.78,86.73 55.87,87.63 52.07,87.63
PIRQ_A_L: length 18.5
  LAYER_3 w0.127: 72.39,129.54 60.97,129.54 60.06,130.44 59.32,130.44 58.41,129.54 54.61,129.54
PIRQ_B_L: length 24.7
  LAYER_3 w0.127: 57.15,130.81 73.65,130.81 74.56,129.91 75.3,129.91 76.21,130.81 77.48,130.81 78.37,129.91 78.37,129.91 80.01,128.27
PIRQ_C_L: length 16.5
  LAYER_8 w0.127: 74.93,130.81 73.66,129.54 73.66,129.53 72.76,128.64 72.02,128.64 71.11,129.54 59.69,129.54
PIRQ_D_L: length 27.4
  LAYER_3 w0.127: 52.07,128.27 55.87,128.27 56.78,127.37 57.52,127.37 58.43,128.27 73.65,128.27 74.56,127.37 75.3,127.37 76.2,128.26 76.2,128.27 77.47,129.54
PIRQ_E_L: length 1.8
  TOP w0.127: 69.19,29.21 68.61,28.63 U3D1.G14 68.77,28.77 68.77,28.78 68.9,28.91 69.19,29.21
PLOCK_L: length 56.8
  TOP w0.127: 54.61,88.9 58.41,88.9 59.32,88 60.06,88 60.97,88.9 71.11,88.9 72.02,88 72.76,88 73.67,88.9 91.43,88.9 92.34,88 93.08,88 93.99,88.9 J4B1.B39
  BOTTOM w0.127: J4B1.B39 104.34,88.9 J7A2.12
R_HL_B11: length 1.8
  TOP w0.127: 68.77,19.88 U3D1.P14 68.61,19.74 69.19,20.32 68.9,20.02 68.77,19.89 68.77,19.88
SERR_L: length 58.9
  LAYER_8 w0.127: 52.07,85.09 55.87,85.09 56.78,84.19 57.52,84.19 58.43,85.09 73.65,85.09 74.56,84.19 75.3,84.19 76.21,85.09 93.97,85.09 94.88,84.19 95.62,84.19 96.53,85.09 100.33,85.09
  BOTTOM w0.127: J7A2.13 105.38,85.09 100.33,85.09
STOP_L: length 38.8
  TOP w0.127: 95.25,90.17 81.29,90.17 80.38,89.27 79.64,89.27 78.73,90.17 57.15,90.17
TCLK: length 50.5
  LAYER_6 w0.127: 100.33,135.89 99.96,135.52 97.42,135.52 96.88,134.99 94.88,134.99 93.97,135.89 76.21,135.89 75.3,134.99 74.56,134.99 73.65,135.89 58.43,135.89 57.52,134.99 56.78,134.99 55.87,135.89 52.07,135.89
TDI: length 38.8
  LAYER_6 w0.127: 57.15,133.35 78.73,133.35 79.64,132.45 91.8,132.45 92.34,132.98 94.88,132.98 95.25,133.35
TMS: length 33.8
  LAYER_6 w0.127: 59.69,134.62 76.19,134.62 77.1,133.72 79.1,133.72 79.64,134.25 92.34,134.25 92.71,134.62
TP_HP_INTR_L: length 1.8
  TOP w0.127: 59.37,16.21 59.08,16.51 59.66,15.93 59.69,15.88 59.5,16.07 59.5,16.08 59.37,16.21
TP_HP_SIC: length 0.8
  TOP w0.127: 53.37,15.85 52.78,16.43
TP_HP_SILB: length 0.9
  TOP w0.127: 54,17.7 54.58,17.12 U3D1.T3
TP_HP_SOC: length 1.8
  TOP w0.127: 56.96,21.15 U3D1.N5 57.12,21.01 56.54,21.59 56.83,21.29 56.96,21.16 56.96,21.15
TP_HP_SOD: length 1.8
  TOP w0.127: 56.54,17.78 57.12,17.2 U3D1.T5 56.96,17.34 56.96,17.35 56.83,17.48 56.54,17.78
TP_HP_SOL: length 1.8
  TOP w0.127: 56.54,20.32 56.83,20.02 56.96,19.89 56.96,19.88 U3D1.P5 57.12,19.74 56.54,20.32
TP_HP_SOLR: length 1.8
  TOP w0.127: 56.83,18.75 56.54,19.05 57.12,18.47 57.15,18.41 56.96,18.61 56.96,18.62 56.83,18.75
TP_HP_SORB: length 0.8
  TOP w0.127: 55.3,17.73 U3D1.T4
TP_HP_SORRB: length 0.9
  TOP w0.127: 55.27,16.46 55.85,15.88 55.88,15.88
TP_P64H_A6: length 1.8
  TOP w0.127: 58.23,36.4 58.23,36.39 U3D1.A6 58.39,36.25 57.81,36.83 58.1,36.53 58.23,36.4
TP_P64H_A16: length 1.8
  TOP w0.127: 71.15,36.25 71.73,36.83 71.44,36.53 71.31,36.4 71.31,36.39 U3D1.A16 71.15,36.25
TP_P64H_B15: length 1.8
  TOP w0.127: 70.04,35.12 70.04,35.13 70.17,35.26 70.46,35.56 69.88,34.98 U3D1.B15 70.04,35.12
TP_P64H_B16: length 1.8
  TOP w0.127: U3D1.B16 71.31,35.12 71.31,35.13 71.44,35.26 71.73,35.56 71.15,34.98 U3D1.B16
TP_P64H_C5: length 1.8
  TOP w0.127: 56.96,33.85 56.96,33.86 56.83,33.99 56.54,34.29 57.12,33.71 U3D1.C5 56.96,33.85
TP_P64H_C15: length 1.8
  TOP w0.127: U3D1.C15 70.04,33.85 70.04,33.86 70.17,33.99 70.46,34.29 69.88,33.71 U3D1.C15
TP_P64H_D5: length 1.8
  TOP w0.127: U3D1.D5 56.96,32.58 56.96,32.59 56.83,32.72 56.54,33.02 57.12,32.44 U3D1.D5
TP_P64H_D15: length 1.8
  TOP w0.127: U3D1.D15 70.04,32.58 70.04,32.59 70.17,32.72 70.46,33.02 69.88,32.44 U3D1.D15
TP_P64H_D17: length 1.8
  TOP w0.127: 72.58,32.59 72.71,32.72 73,33.02 72.42,32.44 U3D1.D17 72.58,32.58 72.58,32.59
TP_P64H_E6: length 1.8
  TOP w0.127: 58.23,31.32 58.1,31.45 57.81,31.75 58.39,31.17 U3D1.E6 58.23,31.31 58.23,31.32
TP_P64H_E15: length 1.8
  TOP w0.127: U3D1.E15 70.04,31.31 70.04,31.32 70.17,31.45 70.46,31.75 69.88,31.17 U3D1.E15
TP_P64H_E16: length 1.8
  TOP w0.127: 71.31,31.32 71.44,31.45 71.73,31.75 71.15,31.17 U3D1.E16 71.31,31.31 71.31,31.32
TP_P64H_E17: length 1.8
  TOP w0.127: 72.58,31.32 72.71,31.45 73,31.75 72.42,31.17 U3D1.E17 72.58,31.31 72.58,31.32
TP_P64H_F15: length 1.8
  TOP w0.127: 70.46,30.48 69.88,29.9 U3D1.F15 70.04,30.04 70.04,30.05 70.17,30.18 70.46,30.48
TP_P64H_F17: length 1.8
  TOP w0.127: 72.58,30.05 72.71,30.18 73,30.48 72.42,29.9 U3D1.F17 72.58,30.04 72.58,30.05
TP_P64H_R6: length 1.8
  TOP w0.127: 58.1,18.75 58.23,18.62 58.23,18.61 58.42,18.41 58.39,18.47 57.81,19.05 58.1,18.75
TP_P64H_R7: length 1.8
  TOP w0.127: 59.5,18.61 59.5,18.62 59.37,18.75 59.08,19.05 59.66,18.47 59.69,18.41 59.5,18.61
TP_P64H_T6: length 1.8
  TOP w0.127: 58.39,17.2 U3D1.T6 58.23,17.34 58.23,17.35 58.1,17.48 57.81,17.78 58.39,17.2
TP_P64H_TEST: length 1.8
  TOP w0.127: U3D1.J16 71.31,26.23 71.31,26.24 71.44,26.37 71.73,26.67 71.15,26.09 U3D1.J16
TP_P64H_U3: length 0.9
  TOP w0.127: 54.61,15.88 54.58,15.88 54,16.46
TP_P64HR8: length 1.8
  TOP w0.127: 60.64,18.75 60.35,19.05 60.93,18.47 60.96,18.41 60.77,18.61 60.77,18.62 60.64,18.75
TP_P66_PCIRST_L_R: length 1.8
  TOP w0.127: 72.58,33.86 72.71,33.99 73,34.29 72.42,33.71 U3D1.C17 72.58,33.85 72.58,33.86
TRDY_L: length 38.8
  TOP w0.127: 95.25,92.71 81.29,92.71 80.38,91.81 79.64,91.81 78.73,92.71 57.15,92.71
TRST: length 33.8
  LAYER_6 w0.127: 59.69,137.16 72.39,137.16 72.76,136.79 75.3,136.79 75.84,136.26 77.84,136.26 78.75,137.16 92.71,137.16

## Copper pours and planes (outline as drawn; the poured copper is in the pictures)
GND on LAYER_7_P, LAYER_9_P: 3.81,146.69 3.81,3.81 118.11,3.81 118.11,146.69
GND on LAYER_8: 21.62,121.34 21.62,109.83 44.15,109.83 44.15,121.34
P5V on LAYER_4_P: 3.81,146.69 3.81,3.81 118.11,3.81 118.11,146.69
+3_3V on LAYER_2_P: 3.81,146.69 3.81,3.81 118.11,3.81 118.11,146.69

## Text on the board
TOP: TOP | BOT
Ref Des/Assembly Top: LIB DRIVEN | BACKDRILL
XSECTION_CHART: *  SURFACE | * PASTEMASK_TOP MASK | * SOLDERMASK_TOP MASK | L1 TOP CONDUCTOR | *  DIELECTRIC | L2 LAYER_2_P PLANE | L3 LAYER_3 CONDUCTOR | L4 LAYER_4_P PLANE | L5 LAYER_5 CONDUCTOR | L6 LAYER_6 CONDUCTOR | L7 LAYER_7_P PLANE | L8 LAYER_8 CONDUCTOR | L9 LAYER_9_P PLANE | L10 BOTTOM CONDUCTOR | * SOLDERMASK_BOTTOM MASK | * PASTEMASK_BOTTOM MASK | DESIGN CROSS SECTION CHART | ___________________________ | TOTAL THICKNESS 2.77312 MM | 1-10 | B1-2-3 | B1-3-4 | B10-2-1 | B10-4-3 | B10-6-5 | B10-7-6 | B10-8-7 | B10-9-8
User.45: NOTES: | - MNC_LAYER: MUST-NOT-CUT-LAYER | - MAX_DEPTH: DEPTH FROM START LAYER TO THE | SURFACE OF MUST-NOT-CUT-LAYER | - MFG_STUB : MANUFACTURING STUB LENGTH | FIGURE | BD_SIZE | 0.7112 | 1.3208 | 1.3556 | 1.524 | MNC_LAYER | LAYER_8 | LAYER_3 | TOP | BACKDRILL: BOTTOM to LAYER_9_P | ALL UNITS ARE IN MILLIMETERS | BACKDRILL: TOP to LAYER_2_P | BACKDRILL: BOTTOM to LAYER_2_P | MAX_DEPTH | 0.4902 | 2.5323 | MFG_STUB | - | QTY | 5 | 48 | 41 | 15 | 35 | 127 | 8 | 1 | LAYER_5 | LAYER_6 | BACKDRILL: BOTTOM to LAYER_6 | BACKDRILL: BOTTOM to LAYER_7_P | 1.3944 | 1.1607 | 11 | 2 | FINISHED_SIZE | 0.3556 | 0.9652 | 1.0 | 1.1684 | 2.921 | 3.175 | 2.4384 | 2.4892 | LAYER_7_P | LAYER_4_P | DRILL CHART: TOP to BOTTOM | BACKDRILL: BOTTOM to LAYER_8 | BACKDRILL: BOTTOM to LAYER_4_P | BACKDRILL: TOP to LAYER_3 | TOOL_SIZE | 45 | 52 | 0.7239 | 2.065 | PLATED | NON-PLATED | 228 | 357 | 3 | 368 | 24 | 6 | 104 | 135 | 88 | 132
